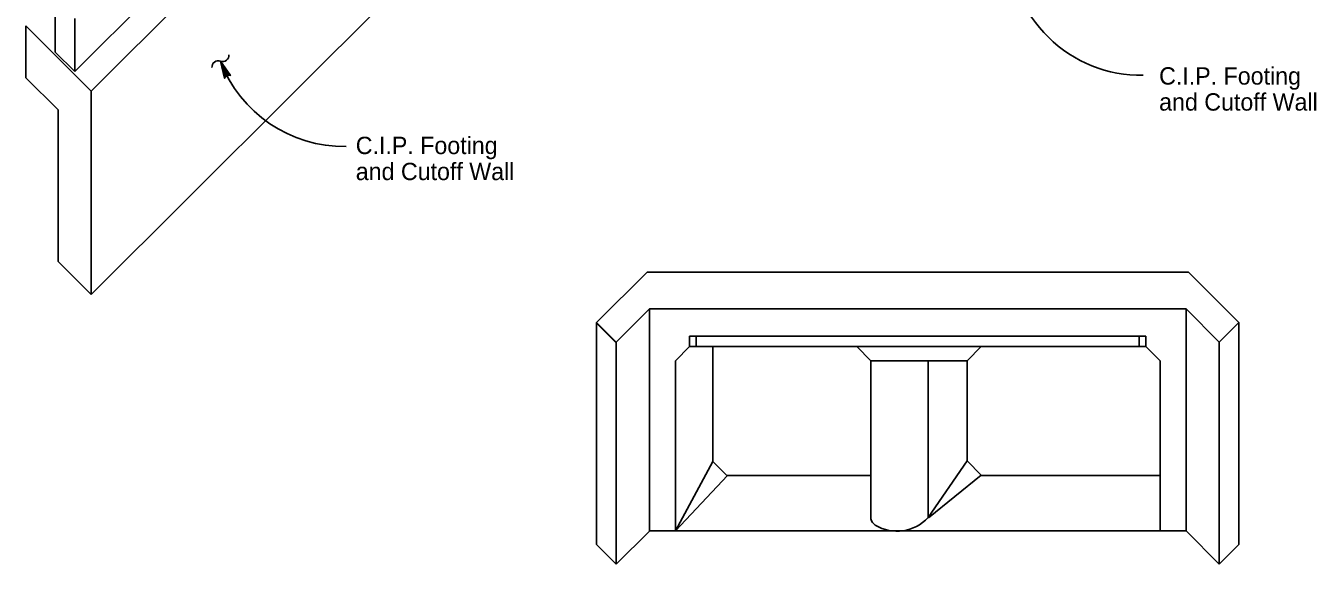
# Model space of a CAD drawing. Extents: x 0 to 2.83, y -0.03 to 1.83.
# Drawn here: x 1.288 to 2.256, y 0.624 to 1.028 of the extents above; entities that cross this region are included whole.
import ezdxf

# ---------------------------------------------------------------- set-up
doc = ezdxf.new("R2010")
doc.units = 0
for name, color, linetype in [('50', 7, 'Continuous'), ('55', 7, 'Continuous'), ('57', 7, 'Continuous'), ('Default', 7, 'Continuous')]:
    doc.layers.add(name, color=color, linetype=linetype)

msp = doc.modelspace()

# ---------------------------------------------------------------- linework, layer by layer
at = {"layer": '50'}
for p, q in [((1.52632, 1.19586), (1.32437, 0.99392)), ((1.75396, 0.84346), (1.71603, 0.8056)), ((2.16016, 0.84346), (2.19806, 0.80557)), ((1.75566, 0.81572), (1.73075, 0.79085)), ((2.15844, 0.81572), (2.18332, 0.79083)), ((1.73045, 0.79055), (1.71572, 0.80528)), ((1.73075, 0.79085), (1.71602, 0.80559)), ((1.73075, 0.79085), (1.71602, 0.80559)), ((2.18332, 0.79083), (2.19806, 0.80557)), ((2.18332, 0.79083), (2.19806, 0.80557)), ((2.12832, 0.7953), (1.78578, 0.7953)), ((1.78578, 0.7953), (1.78578, 0.78749)), ((1.7908, 0.7953), (1.7908, 0.78749)), ((2.12329, 0.7953), (2.12329, 0.78749)), ((2.12832, 0.7953), (2.12832, 0.78749)), ((1.77519, 0.7769), (1.78578, 0.78749)), ((1.92185, 0.7769), (1.91126, 0.78749)), ((1.99406, 0.7769), (2.00464, 0.78749)), ((2.13891, 0.7769), (2.12832, 0.78749)), ((1.8032, 0.70131), (1.77519, 0.64905)), ((1.8032, 0.70131), (1.81361, 0.69089)), ((1.81378, 0.69072), (1.8032, 0.70131)), ((2.00464, 0.69107), (1.99406, 0.70165)), ((1.75566, 0.64901), (1.73075, 0.62411)), ((2.15844, 0.64905), (2.18332, 0.62417)), ((1.73075, 0.62415), (1.71602, 0.63888)), ((2.18332, 0.62417), (2.19806, 0.6389))]:
    msp.add_line(p, q, dxfattribs=at)
at = {"layer": '55'}
for points in [[(1.43376, 1.00179), (1.44121, 0.99097), (1.43904, 0.99126), (1.43499, 0.99904), (1.43813, 0.99082), (1.43689, 0.989), (1.43376, 1.00177)], [(1.43625, 0.99762), (1.43909, 0.99194), (1.44016, 0.99173), (1.43435, 1.00047), (1.43704, 0.99032), (1.4376, 0.99128), (1.4353, 0.99691)]]:
    msp.add_lwpolyline(points, dxfattribs=at)
for centre, radius, start, end in [((2.12471, 1.09028), 0.09915, 179.95619, 270.86046), ((1.43207, 0.99738), 0.0047, 68.91395, 185.32002), ((1.43545, 1.00615), 0.0047, 248.91395, 5.32002), ((1.52651, 1.03681), 0.09915, 200.70097, 270.86046)]:
    msp.add_arc(centre, radius, start, end, dxfattribs=at)
at = {"layer": 'Default'}
for p, q in [((1.56425, 1.20667), (1.3368, 0.97923)), ((1.30964, 1.04858), (1.30964, 1.00865)), ((1.56425, 1.05393), (1.3368, 0.82649)), ((1.2877, 1.02833), (1.2877, 0.98935)), ((1.3368, 0.97923), (1.2877, 1.02833)), ((1.32437, 1.03385), (1.32437, 0.99392)), ((1.32437, 0.99392), (1.30964, 1.00865)), ((1.31188, 0.96517), (1.2877, 0.98935)), ((1.3368, 0.97923), (1.3368, 0.82649)), ((1.31188, 0.96517), (1.31188, 0.85141)), ((1.3368, 0.82649), (1.31188, 0.85141)), ((1.75396, 0.84346), (2.16016, 0.84346)), ((1.75566, 0.81572), (1.75566, 0.64901)), ((1.75566, 0.81572), (2.15844, 0.81572)), ((2.15844, 0.81572), (2.15844, 0.64901)), ((1.71602, 0.80559), (1.71602, 0.63888)), ((2.19806, 0.80557), (2.19806, 0.6389)), ((1.73075, 0.79085), (1.73075, 0.62415)), ((1.78578, 0.78749), (1.91126, 0.78749)), ((1.8032, 0.78749), (1.8032, 0.70131)), ((1.91126, 0.78749), (2.12832, 0.78749)), ((2.18332, 0.79083), (2.18332, 0.62417)), ((1.77519, 0.7769), (1.77519, 0.64905)), ((1.92163, 0.7769), (1.99406, 0.7769)), ((1.92185, 0.7769), (1.92185, 0.65809)), ((1.9648, 0.7769), (1.9648, 0.6591)), ((1.99406, 0.7769), (1.99406, 0.70165)), ((2.13891, 0.7769), (2.13891, 0.64905)), ((1.96483, 0.65907), (1.99406, 0.70165)), ((1.77519, 0.64905), (1.81425, 0.69072)), ((1.81361, 0.69072), (1.92185, 0.69072)), ((2.00464, 0.69107), (1.965, 0.65891)), ((2.00499, 0.69072), (2.13891, 0.69072)), ((1.75566, 0.64905), (2.15844, 0.64905)), ((1.75566, 0.64905), (2.15844, 0.64905))]:
    msp.add_line(p, q, dxfattribs=at)
for centre, radius, start, end in [((1.94158, 0.6803), 0.03144, 238.6242, 317.59844), ((1.92875, 0.65958), 0.00707, 192.18741, 239.94185)]:
    msp.add_arc(centre, radius, start, end, dxfattribs=at)

# ---------------------------------------------------------------- texts
at = {"layer": '57'}
for s, p in [('C.I.P. Footing', (2.13819, 0.98418)), ('and Cutoff Wall', (2.13819, 0.96465)), ('C.I.P. Footing', (1.53531, 0.932)), ('and Cutoff Wall', (1.53531, 0.91247))]:
    msp.add_text(s, height=0.0130208, dxfattribs=at).set_placement(p)

doc.saveas('drawing.dxf')
